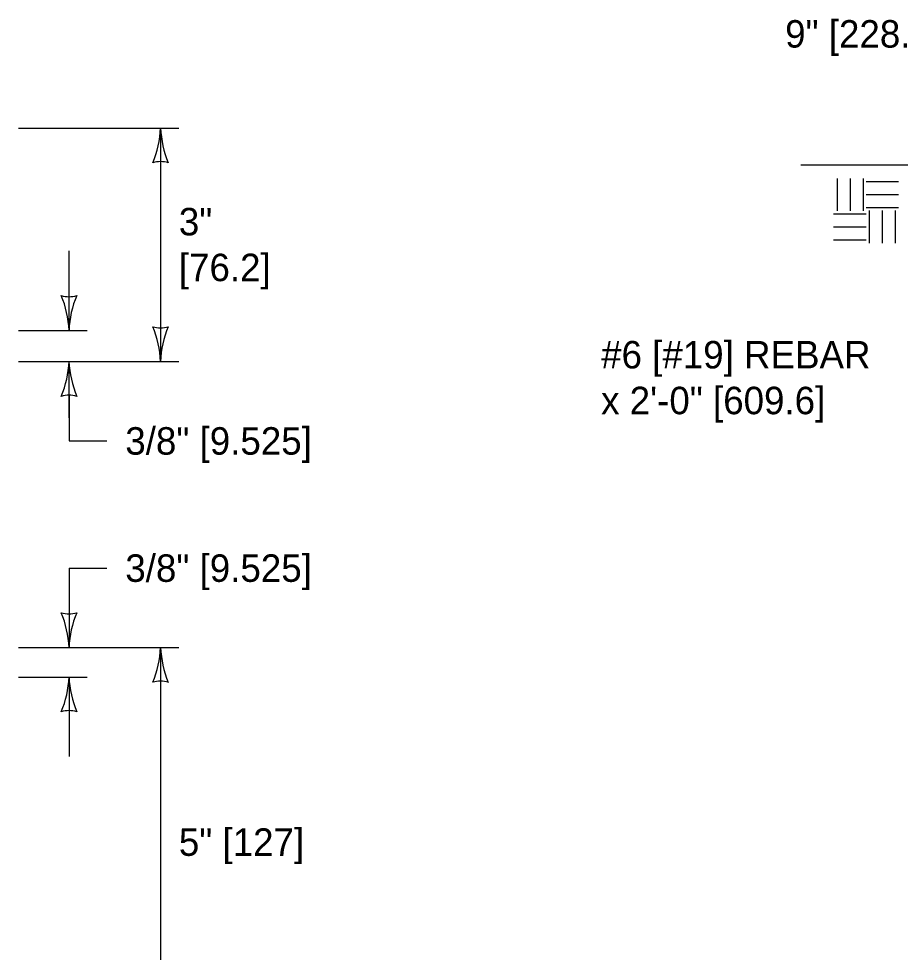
# Model space of a CAD drawing. Extents: x 49991.4 to 50021, y 49987.6 to 50011.4.
# Drawn here: x 50008.716 to 50010.642, y 49990.781 to 49992.82 of the extents above; entities that cross this region are included whole.
import ezdxf

# ---------------------------------------------------------------- set-up
doc = ezdxf.new("R2010")
doc.units = 0
for name, color, linetype in [('Level 1', 7, 'Continuous'), ('Level 2', 7, 'Continuous'), ('Level 3', 7, 'Continuous')]:
    doc.layers.add(name, color=color, linetype=linetype)

msp = doc.modelspace()

# ---------------------------------------------------------------- linework, layer by layer
at = {"layer": 'Level 1'}
for p, q in [((50011.0897, 49992.5003), (50010.4249, 49992.5003)), ((50010.5039, 49992.4715), (50010.5039, 49992.4006)), ((50010.5322, 49992.4715), (50010.5322, 49992.4006)), ((50010.5606, 49992.4715), (50010.5606, 49992.4006)), ((50010.5672, 49992.4649), (50010.638, 49992.4649)), ((50010.5672, 49992.4366), (50010.638, 49992.4366)), ((50010.4963, 49992.394), (50010.5672, 49992.394)), ((50010.5672, 49992.4082), (50010.638, 49992.4082)), ((50010.5742, 49992.4011), (50010.5742, 49992.3303)), ((50010.6026, 49992.4011), (50010.6026, 49992.3303)), ((50010.631, 49992.4011), (50010.631, 49992.3303)), ((50010.4963, 49992.3657), (50010.5672, 49992.3657)), ((50010.4963, 49992.3373), (50010.5672, 49992.3373))]:
    msp.add_line(p, q, dxfattribs=at)
at = {"layer": 'Level 3'}
for p, q in [((50008.7155, 49992.5816), (50009.0655, 49992.5816)), ((50009.0255, 49992.5816), (50009.0255, 49992.0716)), ((50008.8255, 49992.1397), (50008.8255, 49992.3131)), ((50008.7155, 49992.1397), (50008.8655, 49992.1397)), ((50008.7155, 49992.0716), (50009.0655, 49992.0716)), ((50008.8255, 49991.9485), (50008.8255, 49992.0716)), ((50008.8255, 49991.9982), (50008.8255, 49991.8982)), ((50008.8255, 49991.8982), (50008.9085, 49991.8982)), ((50008.8255, 49991.6204), (50008.8255, 49991.447)), ((50008.8255, 49991.6204), (50008.9085, 49991.6204)), ((50008.7155, 49991.447), (50009.0655, 49991.447)), ((50009.0255, 49991.447), (50009.0255, 49990.597)), ((50008.7155, 49991.3826), (50008.8655, 49991.3826)), ((50008.8255, 49991.3826), (50008.8255, 49991.2092))]:
    msp.add_line(p, q, dxfattribs=at)
for centre, radius, start, end in [((50008.8034, 49992.5908), 0.2223, 337.456, 357.6395), ((50009.2582, 49992.5931), 0.233, 182.8273, 202.0772), ((50009.0255, 49992.4534), 0.0548, 72.1388, 107.8612), ((50008.8255, 49992.2679), 0.0548, 252.1388, 287.8612), ((50008.5928, 49992.1282), 0.233, 2.8273, 22.0772), ((50009.0476, 49992.1305), 0.2223, 157.456, 177.6395), ((50009.0255, 49992.1998), 0.0548, 252.1388, 287.8612), ((50008.7928, 49992.0601), 0.233, 2.8273, 22.0772), ((50009.2476, 49992.0624), 0.2223, 157.456, 177.6395), ((50008.6034, 49992.0808), 0.2223, 337.456, 357.6395), ((50009.0582, 49992.0831), 0.233, 182.8273, 202.0772), ((50008.8255, 49991.9434), 0.0548, 72.1388, 107.8612), ((50008.8255, 49991.5752), 0.0548, 252.1388, 287.8612), ((50008.5928, 49991.4355), 0.233, 2.8273, 22.0772), ((50009.0476, 49991.4378), 0.2223, 157.456, 177.6395), ((50008.8034, 49991.4562), 0.2223, 337.456, 357.6395), ((50009.2582, 49991.4585), 0.233, 182.8273, 202.0772), ((50008.6034, 49991.3918), 0.2223, 337.456, 357.6395), ((50009.0582, 49991.3941), 0.233, 182.8273, 202.0772), ((50009.0255, 49991.3188), 0.0548, 72.1388, 107.8612), ((50008.8255, 49991.2544), 0.0548, 72.1388, 107.8612)]:
    msp.add_arc(centre, radius, start, end, dxfattribs=at)

# ---------------------------------------------------------------- texts
at = {"layer": 'Level 2'}
for s, p in [('9" [228.6] ±', (50010.3903, 49992.7572)), ('3"', (50009.0655, 49992.3471)), ('[76.2]', (50009.0655, 49992.2471)), ('#6 [#19] REBAR', (50009.9882, 49992.0565)), ('x 2\'-0" [609.6]', (50009.9882, 49991.9565)), ('3/8" [9.525]', (50008.9485, 49991.8682)), ('3/8" [9.525]', (50008.9485, 49991.5904)), ('5" [127]', (50009.0655, 49990.992))]:
    msp.add_text(s, height=0.06, dxfattribs=at).set_placement(p)

doc.saveas('drawing.dxf')
